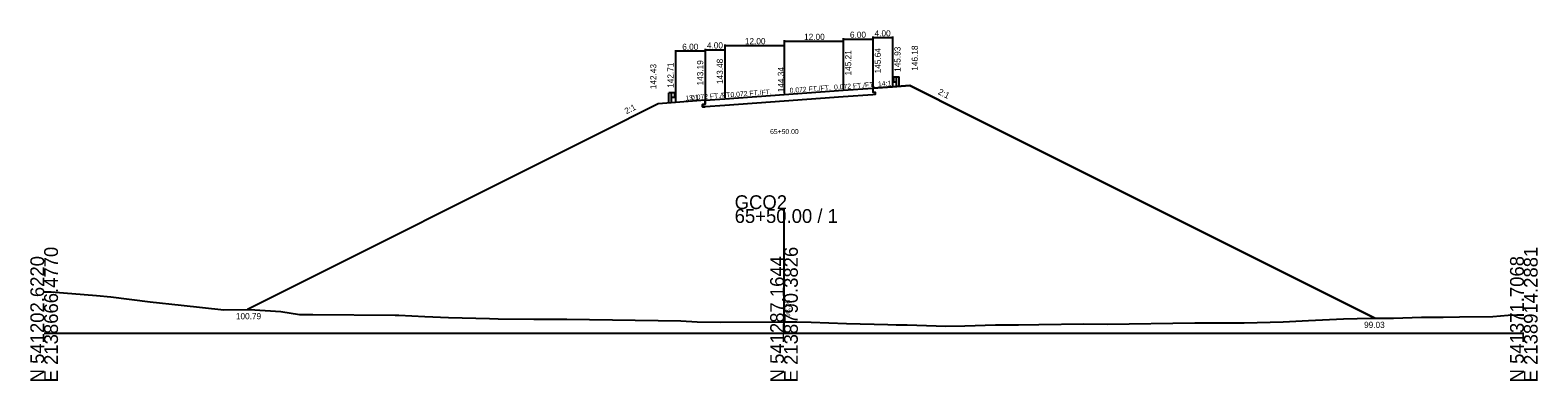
# Model space of a CAD drawing. Extents: x -14327 to 8886, y -10 to 39048.
# Drawn here: x 1997.2 to 2302.8, y 30990.3 to 31061.4 of the extents above; entities that cross this region are included whole.
import ezdxf

# ---------------------------------------------------------------- set-up
doc = ezdxf.new("R2010")
doc.units = 0
for name, color, linetype in [('Level 1', 7, 'Continuous'), ('Level 5', 7, 'Continuous'), ('Level 53', 7, 'Continuous'), ('Level 54', 7, 'Continuous'), ('Level 55', 7, 'Continuous'), ('Level 7', 7, 'Continuous'), ('RD_GPK_XS_Cell', 7, 'Continuous'), ('RD_XS_EwShp', 7, 'Continuous'), ('RD_XS_ExGround', 7, 'Continuous'), ('RD_XS_Pave', 7, 'Continuous'), ('RD_XS_TX_Elev_EX', 7, 'Continuous'), ('RD_XS_TX_Elev_PR', 7, 'Continuous'), ('RD_XS_TX_Station', 7, 'Continuous')]:
    doc.layers.add(name, color=color, linetype=linetype)

msp = doc.modelspace()

# ---------------------------------------------------------------- linework, layer by layer
at = {"layer": 'Level 1'}
for p, q in [((2172.02, 31051.74), (2172.14, 31051.83)), ((2172.02, 31051.64), (2172.14, 31051.55)), ((2172.02, 31051.21), (2172.14, 31051.31)), ((2172.15, 31051.84), (2172.23, 31051.85)), ((2172.16, 31051.5), (2172.16, 31051.35)), ((2172.23, 31051.91), (2172.23, 31050.94)), ((2172.23, 31051.91), (2172.78, 31051.91)), ((2172.78, 31049.93), (2172.78, 31051.91)), ((2172.78, 31051.91), (2173.34, 31051.91)), ((2173.34, 31049.93), (2173.34, 31051.91)), ((2126.66, 31046.71), (2126.66, 31048.7)), ((2127.22, 31048.7), (2126.66, 31048.7)), ((2127.22, 31046.71), (2127.22, 31048.7)), ((2127.77, 31048.7), (2127.22, 31048.7)), ((2127.77, 31048.7), (2127.77, 31047.73)), ((2127.85, 31048.62), (2127.77, 31048.64)), ((2127.84, 31048.29), (2127.84, 31048.14)), ((2127.98, 31048.53), (2127.86, 31048.62)), ((2127.98, 31048.43), (2127.86, 31048.34)), ((2127.98, 31048), (2127.86, 31048.09)), ((2172.02, 31051.11), (2172.14, 31051.02)), ((2172.15, 31051.02), (2172.23, 31051)), ((2172.23, 31050.94), (2172.78, 31050.94)), ((2127.77, 31047.73), (2127.22, 31047.73)), ((2127.85, 31047.8), (2127.77, 31047.79)), ((2127.98, 31047.9), (2127.86, 31047.81))]:
    msp.add_line(p, q, dxfattribs=at)
for centre, radius, start, end in [((2172.07, 31051.69), 0.0651, 129.0336, 230.9663), ((2172.07, 31051.16), 0.0651, 129.0336, 230.9663), ((2172.09, 31051.35), 0.0651, 302.9895, 0), ((2172.15, 31051.81), 0.026, 90, 129.0505), ((2172.09, 31051.5), 0.0651, 0, 45), ((2127.91, 31048.29), 0.0651, 135, 180), ((2127.91, 31048.14), 0.0651, 180, 237.0105), ((2127.85, 31048.6), 0.026, 50.9495, 90), ((2127.93, 31048.48), 0.0651, 309.0337, 50.9664), ((2172.15, 31051.04), 0.026, 230.9496, 270), ((2127.85, 31047.83), 0.026, 270, 309.0504), ((2127.93, 31047.95), 0.0651, 309.0337, 50.9664)]:
    msp.add_arc(centre, radius, start, end, dxfattribs=at)
at = {"layer": 'Level 5'}
for p, q in [((2168, 31048.31), (2162, 31047.87)), ((2168, 31049.64), (2168, 31048.81)), ((2168, 31048.81), (2168.5, 31048.84)), ((2168.5, 31048.34), (2168, 31048.31)), ((2168.5, 31048.84), (2168.5, 31048.34)), ((2134, 31046.36), (2133.5, 31046.32)), ((2133.5, 31046.32), (2133.5, 31045.82)), ((2133.5, 31045.82), (2134, 31045.86)), ((2134, 31047.19), (2134, 31046.36)), ((2138, 31046.15), (2134, 31045.86)), ((2150, 31047.01), (2138, 31046.15)), ((2162, 31047.87), (2150, 31047.01))]:
    msp.add_line(p, q, dxfattribs=at)
at = {"layer": 'Level 54'}
for p, q in [((2128, 31057.34), (2128, 31046.91)), ((2134, 31057.63), (2134, 31047.39)), ((2134, 31057.43), (2138, 31057.43)), ((2134, 31057.34), (2134, 31047.39)), ((2138, 31058.49), (2138, 31047.68)), ((2138, 31058.29), (2150, 31058.29)), ((2138, 31057.63), (2138, 31047.68)), ((2150, 31059.36), (2150, 31048.54)), ((2150, 31059.16), (2162, 31059.16)), ((2150, 31058.49), (2150, 31048.54)), ((2162, 31059.79), (2162, 31049.41)), ((2162, 31059.59), (2168, 31059.59)), ((2162, 31059.36), (2162, 31049.41)), ((2168, 31060.08), (2168, 31049.84)), ((2168, 31059.88), (2172, 31059.88)), ((2168, 31059.79), (2168, 31049.84)), ((2172, 31060.08), (2172, 31050.13)), ((2134, 31057.14), (2128, 31057.14))]:
    msp.add_line(p, q, dxfattribs=at)
at = {"layer": 'Level 7'}
for p, q in [((2168, 31049.64), (2172, 31049.93)), ((2172, 31049.93), (2175.5, 31050.18)), ((2175.5, 31050.18), (2187.5, 31044.18)), ((2124.5, 31046.43), (2112.5, 31040.43)), ((2128, 31046.71), (2124.5, 31046.43)), ((2134, 31047.19), (2128, 31046.71)), ((2187.5, 31044.18), (2269.79, 31003.03)), ((2112.5, 31040.43), (2041.22, 31004.79))]:
    msp.add_line(p, q, dxfattribs=at)
at = {"layer": 'RD_GPK_XS_Cell'}
for p, q in [((2150, 31000), (2150, 31025.12)), ((2000, 31000), (2150, 31000)), ((2150, 31000), (2300, 31000))]:
    msp.add_line(p, q, dxfattribs=at)
at = {"layer": 'RD_XS_EwShp'}
msp.add_lwpolyline([(2128, 31046.71), (2124.5, 31046.43), (2112.5, 31040.43), (2041.22, 31004.79), (2041.66, 31004.8), (2047.99, 31004.36), (2051.75, 31003.77), (2054.47, 31003.75), (2071.18, 31003.63), (2071.91, 31003.61), (2077.16, 31003.37), (2081.99, 31003.14), (2090.31, 31002.95), (2092.07, 31002.88), (2099.25, 31002.81), (2102.16, 31002.83), (2103.92, 31002.82), (2105.95, 31002.79), (2129.07, 31002.44), (2132.4, 31002.28), (2137.14, 31002.19), (2150, 31002.26), (2152.57, 31002.27), (2155.48, 31002.18), (2162.65, 31001.92), (2171.05, 31001.7), (2172.73, 31001.67), (2174.94, 31001.64), (2182.81, 31001.41), (2186.69, 31001.45), (2192.89, 31001.66), (2197.57, 31001.65), (2201.69, 31001.73), (2210.8, 31001.87), (2215.49, 31001.8), (2233.3, 31002.07), (2243.3, 31002.04), (2251.22, 31002.27), (2256.34, 31002.55), (2263.47, 31002.86), (2268.98, 31003.03), (2269.79, 31003.03), (2187.5, 31044.18), (2175.5, 31050.18), (2172, 31049.93), (2168, 31049.64), (2168, 31048.81), (2168.5, 31048.84), (2168.5, 31048.34), (2168, 31048.31), (2162, 31047.87), (2150, 31047.01), (2138, 31046.15), (2134, 31045.86), (2133.5, 31045.82), (2133.5, 31046.32), (2134, 31046.36), (2134, 31047.19)], close=True, dxfattribs=at)
at = {"layer": 'RD_XS_ExGround'}
for p, q in [((2000, 31008.37), (2001.44, 31008.32)), ((2001.44, 31008.32), (2010.61, 31007.61)), ((2010.61, 31007.61), (2013.53, 31007.37)), ((2013.53, 31007.37), (2021.5, 31006.34)), ((2021.5, 31006.34), (2027.8, 31005.63)), ((2027.8, 31005.63), (2036.44, 31004.72)), ((2036.44, 31004.72), (2041.66, 31004.8)), ((2041.66, 31004.8), (2047.99, 31004.36)), ((2047.99, 31004.36), (2051.75, 31003.77)), ((2051.75, 31003.77), (2054.47, 31003.75)), ((2054.47, 31003.75), (2071.18, 31003.63)), ((2071.18, 31003.63), (2071.91, 31003.61)), ((2071.91, 31003.61), (2077.16, 31003.37)), ((2077.16, 31003.37), (2081.99, 31003.14)), ((2081.99, 31003.14), (2090.31, 31002.95)), ((2090.31, 31002.95), (2092.07, 31002.88)), ((2092.07, 31002.88), (2099.25, 31002.81)), ((2099.25, 31002.81), (2102.16, 31002.83)), ((2102.16, 31002.83), (2103.92, 31002.82)), ((2103.92, 31002.82), (2105.95, 31002.79)), ((2105.95, 31002.79), (2129.07, 31002.44)), ((2129.07, 31002.44), (2132.4, 31002.28)), ((2132.4, 31002.28), (2137.14, 31002.19)), ((2137.14, 31002.19), (2150, 31002.26)), ((2150, 31002.26), (2152.57, 31002.27)), ((2152.57, 31002.27), (2155.48, 31002.18)), ((2243.3, 31002.04), (2251.22, 31002.27)), ((2251.22, 31002.27), (2256.34, 31002.55)), ((2256.34, 31002.55), (2263.47, 31002.86)), ((2263.47, 31002.86), (2268.98, 31003.03)), ((2268.98, 31003.03), (2273.55, 31003.02)), ((2273.55, 31003.02), (2279.26, 31003.19)), ((2279.26, 31003.19), (2283.63, 31003.24)), ((2283.63, 31003.24), (2286.94, 31003.3)), ((2286.94, 31003.3), (2293.71, 31003.37)), ((2293.71, 31003.37), (2296.84, 31003.64)), ((2296.84, 31003.64), (2298.61, 31003.71)), ((2298.61, 31003.71), (2300, 31003.72)), ((2155.48, 31002.18), (2162.65, 31001.92)), ((2162.65, 31001.92), (2171.05, 31001.7)), ((2171.05, 31001.7), (2172.73, 31001.67)), ((2172.73, 31001.67), (2174.94, 31001.64)), ((2174.94, 31001.64), (2182.81, 31001.41)), ((2182.81, 31001.41), (2186.69, 31001.45)), ((2186.69, 31001.45), (2192.89, 31001.66)), ((2192.89, 31001.66), (2197.57, 31001.65)), ((2197.57, 31001.65), (2201.69, 31001.73)), ((2201.69, 31001.73), (2210.8, 31001.87)), ((2210.8, 31001.87), (2215.49, 31001.8)), ((2215.49, 31001.8), (2233.3, 31002.07)), ((2233.3, 31002.07), (2243.3, 31002.04))]:
    msp.add_line(p, q, dxfattribs=at)
at = {"layer": 'RD_XS_Pave'}
for p, q in [((2138, 31047.48), (2150, 31048.34)), ((2150, 31048.34), (2162, 31049.21)), ((2162, 31049.21), (2168, 31049.64)), ((2134, 31047.19), (2138, 31047.48))]:
    msp.add_line(p, q, dxfattribs=at)

# ---------------------------------------------------------------- texts
at = {"layer": 'Level 53'}
for s, rotation, p in [('145.64', 90, (2169.63, 31052.64)), ('145.93', 90, (2173.63, 31052.93)), ('146.18', 90, (2177.13, 31053.18)), ('142.43', 90, (2124.12, 31049.43)), ('142.71', 90, (2127.62, 31049.71)), ('143.19', 90, (2133.62, 31050.19)), ('143.48', 90, (2137.62, 31050.48)), ('145.21', 90, (2163.63, 31052.21)), ('2:1', 333.4349, (2181.11, 31048.49)), ('2:1', 26.5651, (2118.05, 31044.33))]:
    msp.add_text(s, height=1.25, rotation=rotation, dxfattribs=at).set_placement(p)
for s, p in [('100.79', (2038.87, 31002.79)), ('99.03', (2267.61, 31001.03))]:
    msp.add_text(s, height=1.25, dxfattribs=at).set_placement(p)
at = {"layer": 'Level 54'}
for s, p in [('12.00', (2154.07, 31059.41)), ('6.00', (2163.37, 31059.84)), ('4.00', (2168.37, 31060.13)), ('6.00', (2129.37, 31057.39)), ('4.00', (2134.37, 31057.68)), ('12.00', (2142.07, 31058.54))]:
    msp.add_text(s, height=1.25, dxfattribs=at).set_placement(p)
at = {"layer": 'Level 55'}
for s, rotation, p in [('14:1', 4.1182, (2169.08, 31049.97)), ('13:1', 4.5739, (2130.03, 31047.12)), ('0.072 FT./FT.', 4.1182, (2131.18, 31047.24)), ('0.072 FT./FT.', 4.1182, (2139.18, 31047.81)), ('0.072 FT./FT.', 4.1182, (2151.18, 31048.68)), ('0.072 FT./FT.', 4.1182, (2160.18, 31049.33))]:
    msp.add_text(s, height=1, rotation=rotation, dxfattribs=at).set_placement(p)
at = {"layer": 'RD_GPK_XS_Cell'}
for s, p in [('GCO2', (2140, 31025.12)), ('65+50.00 / 1', (2140, 31022.32))]:
    msp.add_text(s, height=2.8, dxfattribs=at).set_placement(p)
for s, p in [('N 541202.6220', (2000, 30990)), ('E 2138666.4770', (2002.8, 30990)), ('N 541287.1644', (2150, 30990)), ('E 2138790.3826', (2152.8, 30990)), ('N 541371.7068', (2300, 30990)), ('E 2138914.2881', (2302.8, 30990))]:
    msp.add_text(s, height=2.8, rotation=90, dxfattribs=at).set_placement(p)
at = {"layer": 'RD_XS_TX_Elev_EX'}
msp.add_text('98.26', height=1, rotation=90, dxfattribs=at).set_placement((2151.25, 31003.26))
at = {"layer": 'RD_XS_TX_Elev_PR'}
msp.add_text(' 144.34', height=1.25, rotation=90, dxfattribs=at).set_placement((2150, 31048.34))
at = {"layer": 'RD_XS_TX_Station'}
msp.add_text('65+50.00', height=1, dxfattribs=at).set_placement((2147.18, 31040.34))

doc.saveas('drawing.dxf')
